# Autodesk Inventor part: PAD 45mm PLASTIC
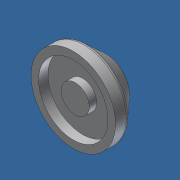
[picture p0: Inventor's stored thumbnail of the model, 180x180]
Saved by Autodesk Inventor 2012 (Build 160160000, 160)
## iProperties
Created: 2007-03
Part Number: PAD 45mm PLASTIC
Document SubType Name: Modeling
Designer: Andy Moles
Material: ABS Plastic
Mass: 16.1926 g
Surface Area: 57.8063 cm^2
Volume: 15.276 cm^3
Density: 1.06 g/cm^3
Author: Andy Moles
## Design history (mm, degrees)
sketch "Sketch1"
  geometry: L1 (0, 0)-(22.5, 0); L2 (22.5, 0)-(22.5, 5.724); L3 (0, 0)-(0, 18); L4 (6.633, 18)-(11.118, 18); L5 (21.977, 7.073)-(12.595, 17.349); L6 (0, 0)-(0, 7); A1 r 7.5 centre (0, 14.5) between (0, 7) and (6.633, 18); A2 r 2 centre (11.118, 16) between (12.595, 17.349) and (11.118, 18); A3 r 2 centre (20.5, 5.724) between (22.5, 5.724) and (21.977, 7.073); 2 further points
  constraints: 12 end point, 6 point on circle, 6 point on line, 4 tangent, 3 centre point, 2 perpendicular, 1 collinear, 1 equal radius, 1 horizontal, 1 parallel
  dimensions: "d0" = 22.5 distance of L1.start L1.end; "d1" = 6.5 distance of L1.end point (22.5, 6.5); "d2" = 18 distance of L1.start L3.end; "d3" = 15 diameter of A1; "d4" = 3.5 distance of A1.centre L3.end; "d5" = 12 horizontal distance of point (12, 18) L1.start; "d6" = 2 radius of A2
revolve "Revolution1" sketch "Sketch1" stored, may be unused: angle "d7" = 90 deg
sketch "Sketch2"
  geometry: C1 r 22.5 at (0, 0) reference; C2 r 7.5 at (0, 0)
  constraints: 1 centre point, 1 coincident
  dimensions: "d8" = 15 diameter of C2
extrude "Extrusion1" cut sketch "Sketch2" distance "d9" = 1; taper "d10" = 0 deg
sketch "Sketch3"
  geometry: C1 r 7.5 at (0, 0) reference; C2 r 22.5 at (0, 0) reference; C3 r 18.5 at (0, 0)
  constraints: 1 centre point, 1 coincident
  dimensions: "d11" = 4 radial gap between concentric circles of C2 C3
extrude "Extrusion2" cut sketch "Sketch3" distance "d12" = 5; taper "d13" = 0 deg
body "Solid1"
